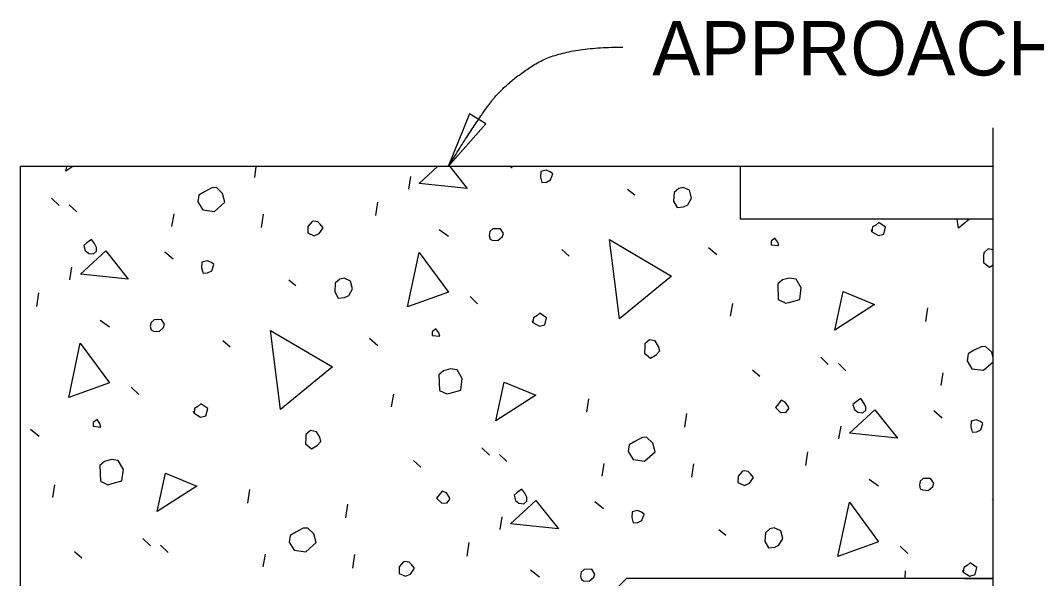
# Model space of a CAD drawing. Extents: x -1660015.2 to -1659984.9, y 2580594.2 to 2580616.7.
# Drawn here: x -1659989.349 to -1659986.525, y 2580613.05 to 2580614.602 of the extents above; entities that cross this region are included whole.
import ezdxf

# ---------------------------------------------------------------- set-up
doc = ezdxf.new("R2010")
doc.units = 0
for name, color, linetype in [('Miscellaneous', 7, 'Continuous'), ('Miscellaneous3', 7, 'Continuous'), ('PlotBorder_dp', 7, 'Continuous'), ('SheetLines_dp', 7, 'Continuous')]:
    doc.layers.add(name, color=color, linetype=linetype)

msp = doc.modelspace()

# ---------------------------------------------------------------- linework, layer by layer
at = {"layer": 'Miscellaneous'}
for p, q in [((-1659988.698, 2580614.1655), (-1659988.6937, 2580614.1954)), ((-1659987.9875, 2580614.1954), (-1659987.9829, 2580614.1915)), ((-1659986.6457, 2580614.1954), (-1659987.3492, 2580614.1954)), ((-1659988.27, 2580614.1327), (-1659988.2639, 2580614.1679)), ((-1659987.6617, 2580614.1326), (-1659987.642, 2580614.1172)), ((-1659989.2622, 2580614.1075), (-1659989.2413, 2580614.0872)), ((-1659989.2134, 2580614.0895), (-1659989.1925, 2580614.0692)), ((-1659988.3615, 2580614.059), (-1659988.3561, 2580614.0967)), ((-1659988.928, 2580614.0288), (-1659988.9219, 2580614.0641)), ((-1659988.6787, 2580614.0257), (-1659988.6733, 2580614.0634)), ((-1659988.1856, 2580614.0207), (-1659988.1598, 2580614.0017)), ((-1659988.948, 2580613.9587), (-1659988.9247, 2580613.9391)), ((-1659987.8444, 2580613.9646), (-1659987.8241, 2580613.9467)), ((-1659987.437, 2580613.9702), (-1659987.4136, 2580613.9506)), ((-1659989.2117, 2580613.8803), (-1659989.2057, 2580613.9156)), ((-1659988.6035, 2580613.8802), (-1659988.5838, 2580613.8648)), ((-1659989.3033, 2580613.8066), (-1659989.2978, 2580613.8443)), ((-1659988.0994, 2580613.8341), (-1659988.0784, 2580613.8139)), ((-1659987.3756, 2580613.7796), (-1659987.3695, 2580613.8149)), ((-1659986.8332, 2580613.7645), (-1659986.8278, 2580613.8022)), ((-1659989.1274, 2580613.7683), (-1659989.1016, 2580613.7494)), ((-1659988.7862, 2580613.7122), (-1659988.7659, 2580613.6944)), ((-1659988.3788, 2580613.7179), (-1659988.3554, 2580613.6982)), ((-1659987.125, 2580613.6656), (-1659987.1041, 2580613.6453)), ((-1659987.0762, 2580613.6476), (-1659987.0553, 2580613.6273)), ((-1659987.3149, 2580613.6302), (-1659987.2946, 2580613.6124)), ((-1659986.7908, 2580613.5869), (-1659986.7847, 2580613.6222)), ((-1659989.0412, 2580613.5818), (-1659989.0202, 2580613.5615)), ((-1659988.3174, 2580613.5273), (-1659988.3113, 2580613.5625)), ((-1659987.775, 2580613.5121), (-1659987.7695, 2580613.5498)), ((-1659987.5026, 2580613.4712), (-1659987.4972, 2580613.5089)), ((-1659986.8108, 2580613.5168), (-1659986.7875, 2580613.4972)), ((-1659989.3206, 2580613.4655), (-1659989.2972, 2580613.4459)), ((-1659987.0745, 2580613.4384), (-1659987.0685, 2580613.4737)), ((-1659988.0668, 2580613.4132), (-1659988.0459, 2580613.393)), ((-1659988.018, 2580613.3952), (-1659987.997, 2580613.375)), ((-1659987.1661, 2580613.3647), (-1659987.1606, 2580613.4024)), ((-1659988.2566, 2580613.3779), (-1659988.2363, 2580613.36)), ((-1659987.7326, 2580613.3346), (-1659987.7265, 2580613.3698)), ((-1659987.4833, 2580613.3315), (-1659987.4779, 2580613.3692)), ((-1659989.2592, 2580613.2749), (-1659989.2531, 2580613.3102)), ((-1659986.9902, 2580613.3264), (-1659986.9644, 2580613.3075)), ((-1659988.7168, 2580613.2598), (-1659988.7113, 2580613.2975)), ((-1659988.4444, 2580613.2189), (-1659988.439, 2580613.2566)), ((-1659987.7526, 2580613.2645), (-1659987.7292, 2580613.2449)), ((-1659986.649, 2580613.2703), (-1659986.6457, 2580613.2674)), ((-1659988.0163, 2580613.1861), (-1659988.0102, 2580613.2213)), ((-1659987.4081, 2580613.186), (-1659987.3884, 2580613.1705)), ((-1659989.0086, 2580613.1609), (-1659988.9876, 2580613.1406)), ((-1659988.9598, 2580613.1429), (-1659988.9388, 2580613.1226)), ((-1659988.1079, 2580613.1124), (-1659988.1024, 2580613.15)), ((-1659986.904, 2580613.1399), (-1659986.883, 2580613.1196)), ((-1659989.1984, 2580613.1255), (-1659989.1781, 2580613.1077)), ((-1659988.6744, 2580613.0822), (-1659988.6683, 2580613.1175)), ((-1659988.4251, 2580613.0791), (-1659988.4196, 2580613.1168)), ((-1659987.932, 2580613.0741), (-1659987.9062, 2580613.0551)), ((-1659986.7243, 2580613.0496), (-1659986.6457, 2580613.0496))]:
    msp.add_line(p, q, dxfattribs=at)
for points in [[(-1659989.2229, 2580614.1827), (-1659989.2202, 2580614.1954)], [(-1659989.2033, 2580614.1954), (-1659989.2229, 2580614.1827)], [(-1659988.2405, 2580614.1483), (-1659988.1899, 2580614.1954)], [(-1659988.1554, 2580614.1954), (-1659988.1075, 2580614.1348), (-1659988.2405, 2580614.1483)], [(-1659987.9036, 2580614.1661), (-1659987.8997, 2580614.1516), (-1659987.887, 2580614.1524), (-1659987.8756, 2580614.1581), (-1659987.8698, 2580614.1752), (-1659987.8766, 2580614.1811), (-1659987.8882, 2580614.1858), (-1659987.9027, 2580614.1819), (-1659987.9036, 2580614.1661)], [(-1659988.8558, 2580614.0973), (-1659988.8421, 2580614.0751), (-1659988.8098, 2580614.0708), (-1659988.7806, 2580614.0968), (-1659988.787, 2580614.1209), (-1659988.8043, 2580614.137), (-1659988.817, 2580614.1362), (-1659988.8374, 2580614.1255), (-1659988.8531, 2580614.1162), (-1659988.8558, 2580614.0973)], [(-1659987.5324, 2580614.1232), (-1659987.5338, 2580614.0996), (-1659987.5238, 2580614.0815), (-1659987.5062, 2580614.0837), (-1659987.4948, 2580614.0893), (-1659987.4842, 2580614.1077), (-1659987.49, 2580614.1294), (-1659987.5078, 2580614.1376), (-1659987.5198, 2580614.1344), (-1659987.5324, 2580614.1232)], [(-1659988.5502, 2580614.0291), (-1659988.5505, 2580614.0109), (-1659988.5328, 2580614.0027), (-1659988.5189, 2580614.009), (-1659988.5077, 2580614.025), (-1659988.5157, 2580614.0357), (-1659988.5225, 2580614.0417), (-1659988.5335, 2580614.0439), (-1659988.5383, 2580614.0426), (-1659988.5502, 2580614.0291)], [(-1659986.7424, 2580614.0243), (-1659986.7456, 2580614.0496)], [(-1659986.7118, 2580614.0496), (-1659986.7424, 2580614.0243)], [(-1659988.0438, 2580613.994), (-1659988.0377, 2580613.9904), (-1659988.0219, 2580613.9895), (-1659988.0094, 2580614.0006), (-1659988.0065, 2580614.0091), (-1659988.0152, 2580614.0223), (-1659988.0358, 2580614.022), (-1659988.0442, 2580614.0146), (-1659988.0464, 2580614.0036), (-1659988.0438, 2580613.994)], [(-1659986.9829, 2580614.0142), (-1659986.9646, 2580614.0036), (-1659986.9501, 2580614.0075), (-1659986.945, 2580614.027), (-1659986.964, 2580614.04), (-1659986.9723, 2580614.0326), (-1659986.9813, 2580614.0276), (-1659986.9829, 2580614.0142), (-1659986.9842, 2580614.0191)], [(-1659989.1688, 2580613.9617), (-1659989.159, 2580613.954), (-1659989.1456, 2580613.9524), (-1659989.1373, 2580613.9598), (-1659989.1374, 2580613.9701), (-1659989.1431, 2580613.9815), (-1659989.1512, 2580613.9923), (-1659989.1643, 2580613.9836), (-1659989.1727, 2580613.9762), (-1659989.1688, 2580613.9617)], [(-1659987.6841, 2580613.772), (-1659987.7121, 2580613.9923), (-1659987.54, 2580613.8909), (-1659987.6841, 2580613.772)], [(-1659987.2631, 2580613.978), (-1659987.2418, 2580613.9759), (-1659987.2444, 2580613.9856), (-1659987.2525, 2580613.9964), (-1659987.2633, 2580613.9883), (-1659987.2631, 2580613.978)], [(-1659989.1823, 2580613.896), (-1659989.1118, 2580613.9614), (-1659989.0492, 2580613.8824), (-1659989.1823, 2580613.896)], [(-1659986.6457, 2580613.9635), (-1659986.6595, 2580613.9663), (-1659986.6721, 2580613.9552), (-1659986.6725, 2580613.9473)], [(-1659988.8454, 2580613.9138), (-1659988.8415, 2580613.8993), (-1659988.8288, 2580613.9001), (-1659988.8174, 2580613.9058), (-1659988.8116, 2580613.9228), (-1659988.8184, 2580613.9288), (-1659988.83, 2580613.9334), (-1659988.8445, 2580613.9296), (-1659988.8454, 2580613.9138)], [(-1659988.2729, 2580613.8058), (-1659988.2409, 2580613.9567), (-1659988.1596, 2580613.8465), (-1659988.2729, 2580613.8058)], [(-1659986.6725, 2580613.9473), (-1659986.6728, 2580613.9291), (-1659986.6562, 2580613.9154), (-1659986.6457, 2580613.9218)], [(-1659988.4742, 2580613.8709), (-1659988.4756, 2580613.8472), (-1659988.4656, 2580613.8292), (-1659988.448, 2580613.8313), (-1659988.4366, 2580613.837), (-1659988.426, 2580613.8553), (-1659988.4318, 2580613.8771), (-1659988.4495, 2580613.8853), (-1659988.4616, 2580613.882), (-1659988.4742, 2580613.8709)], [(-1659987.2443, 2580613.8691), (-1659987.243, 2580613.8255), (-1659987.2222, 2580613.8155), (-1659987.2101, 2580613.8188), (-1659987.1835, 2580613.8259), (-1659987.1792, 2580613.8581), (-1659987.1936, 2580613.8827), (-1659987.2124, 2580613.8854), (-1659987.2318, 2580613.8803), (-1659987.2443, 2580613.8691)], [(-1659987.0857, 2580613.7408), (-1659987.0626, 2580613.8479), (-1659986.9753, 2580613.8118), (-1659987.0857, 2580613.7408)], [(-1659988.9856, 2580613.7416), (-1659988.9795, 2580613.7381), (-1659988.9637, 2580613.7371), (-1659988.9512, 2580613.7483), (-1659988.9483, 2580613.7568), (-1659988.957, 2580613.77), (-1659988.9776, 2580613.7696), (-1659988.986, 2580613.7622), (-1659988.9882, 2580613.7513), (-1659988.9856, 2580613.7416)], [(-1659987.9247, 2580613.7619), (-1659987.9064, 2580613.7513), (-1659987.8919, 2580613.7552), (-1659987.8867, 2580613.7747), (-1659987.9057, 2580613.7877), (-1659987.9141, 2580613.7803), (-1659987.9231, 2580613.7753), (-1659987.9247, 2580613.7619), (-1659987.926, 2580613.7667)], [(-1659988.6259, 2580613.5196), (-1659988.6539, 2580613.7399), (-1659988.4818, 2580613.6385), (-1659988.6259, 2580613.5196)], [(-1659988.2049, 2580613.7256), (-1659988.1836, 2580613.7236), (-1659988.1862, 2580613.7332), (-1659988.1943, 2580613.744), (-1659988.2051, 2580613.7359), (-1659988.2049, 2580613.7256)], [(-1659989.2147, 2580613.5534), (-1659989.1827, 2580613.7043), (-1659989.1014, 2580613.5941), (-1659989.2147, 2580613.5534)], [(-1659987.6143, 2580613.6949), (-1659987.6146, 2580613.6767), (-1659987.598, 2580613.6631), (-1659987.5824, 2580613.6724), (-1659987.5723, 2580613.6829), (-1659987.5755, 2580613.695), (-1659987.5849, 2580613.7106), (-1659987.6013, 2580613.714), (-1659987.6138, 2580613.7028), (-1659987.6143, 2580613.6949)], [(-1659986.6457, 2580613.6635), (-1659986.6498, 2580613.679), (-1659986.6671, 2580613.6951), (-1659986.6798, 2580613.6943), (-1659986.7002, 2580613.6836), (-1659986.7159, 2580613.6743), (-1659986.7186, 2580613.6554)], [(-1659986.7186, 2580613.6554), (-1659986.7049, 2580613.6332), (-1659986.6726, 2580613.6289), (-1659986.6457, 2580613.6528)], [(-1659988.1861, 2580613.6168), (-1659988.1847, 2580613.5732), (-1659988.1639, 2580613.5632), (-1659988.1519, 2580613.5664), (-1659988.1253, 2580613.5736), (-1659988.121, 2580613.6058), (-1659988.1354, 2580613.6304), (-1659988.1542, 2580613.6331), (-1659988.1735, 2580613.6279), (-1659988.1861, 2580613.6168)], [(-1659988.0275, 2580613.4885), (-1659988.0044, 2580613.5956), (-1659987.9171, 2580613.5595), (-1659988.0275, 2580613.4885)], [(-1659988.8665, 2580613.5095), (-1659988.8481, 2580613.4989), (-1659988.8336, 2580613.5028), (-1659988.8285, 2580613.5223), (-1659988.8475, 2580613.5353), (-1659988.8559, 2580613.5279), (-1659988.8649, 2580613.5229), (-1659988.8665, 2580613.5095), (-1659988.8678, 2580613.5144)], [(-1659987.2507, 2580613.5258), (-1659987.2365, 2580613.5115), (-1659987.2213, 2580613.513), (-1659987.2136, 2580613.5228), (-1659987.2149, 2580613.5276), (-1659987.2236, 2580613.5408), (-1659987.2352, 2580613.5455), (-1659987.2429, 2580613.5356), (-1659987.2507, 2580613.5258)], [(-1659987.0316, 2580613.5198), (-1659987.0218, 2580613.5121), (-1659987.0084, 2580613.5105), (-1659987.0001, 2580613.5179), (-1659987.0002, 2580613.5282), (-1659987.0059, 2580613.5396), (-1659987.014, 2580613.5504), (-1659987.0271, 2580613.5417), (-1659987.0355, 2580613.5343), (-1659987.0316, 2580613.5198)], [(-1659987.0451, 2580613.4541), (-1659986.9746, 2580613.5195), (-1659986.912, 2580613.4405), (-1659987.0451, 2580613.4541)], [(-1659989.1467, 2580613.4733), (-1659989.1254, 2580613.4712), (-1659989.128, 2580613.4809), (-1659989.1361, 2580613.4917), (-1659989.1468, 2580613.4836), (-1659989.1467, 2580613.4733)], [(-1659986.7082, 2580613.4719), (-1659986.7043, 2580613.4574), (-1659986.6916, 2580613.4582), (-1659986.6802, 2580613.4638), (-1659986.6744, 2580613.4809), (-1659986.6812, 2580613.4869), (-1659986.6928, 2580613.4915), (-1659986.7073, 2580613.4876), (-1659986.7082, 2580613.4719)], [(-1659988.5561, 2580613.4426), (-1659988.5564, 2580613.4244), (-1659988.5398, 2580613.4107), (-1659988.5242, 2580613.4201), (-1659988.5141, 2580613.4306), (-1659988.5173, 2580613.4426), (-1659988.5266, 2580613.4582), (-1659988.5431, 2580613.4616), (-1659988.5556, 2580613.4505), (-1659988.5561, 2580613.4426)], [(-1659987.6603, 2580613.4031), (-1659987.6466, 2580613.3809), (-1659987.6144, 2580613.3766), (-1659987.5851, 2580613.4025), (-1659987.5916, 2580613.4267), (-1659987.6089, 2580613.4428), (-1659987.6216, 2580613.4419), (-1659987.642, 2580613.4313), (-1659987.6576, 2580613.4219), (-1659987.6603, 2580613.4031)], [(-1659989.1279, 2580613.3644), (-1659989.1265, 2580613.3208), (-1659989.1057, 2580613.3108), (-1659989.0937, 2580613.3141), (-1659989.0671, 2580613.3212), (-1659989.0628, 2580613.3534), (-1659989.0771, 2580613.378), (-1659989.096, 2580613.3808), (-1659989.1153, 2580613.3756), (-1659989.1279, 2580613.3644)], [(-1659988.9692, 2580613.2361), (-1659988.9462, 2580613.3432), (-1659988.8588, 2580613.3071), (-1659988.9692, 2580613.2361)], [(-1659987.3548, 2580613.3348), (-1659987.3551, 2580613.3166), (-1659987.3374, 2580613.3085), (-1659987.3235, 2580613.3148), (-1659987.3123, 2580613.3307), (-1659987.3203, 2580613.3415), (-1659987.3271, 2580613.3474), (-1659987.338, 2580613.3497), (-1659987.3429, 2580613.3484), (-1659987.3548, 2580613.3348)], [(-1659986.8484, 2580613.2997), (-1659986.8423, 2580613.2962), (-1659986.8265, 2580613.2952), (-1659986.814, 2580613.3063), (-1659986.8111, 2580613.3149), (-1659986.8198, 2580613.3281), (-1659986.8404, 2580613.3277), (-1659986.8488, 2580613.3203), (-1659986.851, 2580613.3094), (-1659986.8484, 2580613.2997)], [(-1659988.1924, 2580613.2735), (-1659988.1782, 2580613.2591), (-1659988.1631, 2580613.2606), (-1659988.1554, 2580613.2704), (-1659988.1567, 2580613.2753), (-1659988.1654, 2580613.2885), (-1659988.177, 2580613.2931), (-1659988.1847, 2580613.2833), (-1659988.1924, 2580613.2735)], [(-1659987.9734, 2580613.2674), (-1659987.9636, 2580613.2597), (-1659987.9502, 2580613.2581), (-1659987.9418, 2580613.2655), (-1659987.942, 2580613.2758), (-1659987.9477, 2580613.2873), (-1659987.9557, 2580613.2981), (-1659987.9689, 2580613.2893), (-1659987.9773, 2580613.2819), (-1659987.9734, 2580613.2674)], [(-1659987.9869, 2580613.2017), (-1659987.9164, 2580613.2672), (-1659987.8538, 2580613.1882), (-1659987.9869, 2580613.2017)], [(-1659987.0775, 2580613.1115), (-1659987.0455, 2580613.2624), (-1659986.9642, 2580613.1522), (-1659987.0775, 2580613.1115)], [(-1659987.65, 2580613.2195), (-1659987.6461, 2580613.205), (-1659987.6334, 2580613.2058), (-1659987.622, 2580613.2115), (-1659987.6162, 2580613.2286), (-1659987.6229, 2580613.2345), (-1659987.6345, 2580613.2392), (-1659987.649, 2580613.2353), (-1659987.65, 2580613.2195)], [(-1659988.6021, 2580613.1507), (-1659988.5884, 2580613.1285), (-1659988.5562, 2580613.1242), (-1659988.5269, 2580613.1502), (-1659988.5334, 2580613.1743), (-1659988.5506, 2580613.1904), (-1659988.5634, 2580613.1896), (-1659988.5838, 2580613.1789), (-1659988.5994, 2580613.1696), (-1659988.6021, 2580613.1507)], [(-1659987.2787, 2580613.1766), (-1659987.2802, 2580613.153), (-1659987.2702, 2580613.1349), (-1659987.2526, 2580613.1371), (-1659987.2412, 2580613.1427), (-1659987.2306, 2580613.1611), (-1659987.2364, 2580613.1828), (-1659987.2541, 2580613.191), (-1659987.2662, 2580613.1878), (-1659987.2787, 2580613.1766)], [(-1659988.2966, 2580613.0825), (-1659988.2969, 2580613.0643), (-1659988.2791, 2580613.0561), (-1659988.2653, 2580613.0624), (-1659988.254, 2580613.0784), (-1659988.2621, 2580613.0891), (-1659988.2689, 2580613.0951), (-1659988.2798, 2580613.0973), (-1659988.2847, 2580613.096), (-1659988.2966, 2580613.0825)], [(-1659986.7293, 2580613.0676), (-1659986.7109, 2580613.057), (-1659986.6964, 2580613.0609), (-1659986.6913, 2580613.0804), (-1659986.7103, 2580613.0934), (-1659986.7187, 2580613.086), (-1659986.7277, 2580613.081), (-1659986.7293, 2580613.0676), (-1659986.7306, 2580613.0725)], [(-1659987.7902, 2580613.0474), (-1659987.7841, 2580613.0438), (-1659987.7683, 2580613.0429), (-1659987.7557, 2580613.054), (-1659987.7529, 2580613.0625), (-1659987.7616, 2580613.0757), (-1659987.7822, 2580613.0754), (-1659987.7906, 2580613.068), (-1659987.7928, 2580613.057), (-1659987.7902, 2580613.0474)], [(-1659986.8906, 2580613.0717), (-1659986.8913, 2580613.0496)], [(-1659987.0721, 2580613.0496), (-1659987.0723, 2580613.0505), (-1659987.0746, 2580613.0496)], [(-1659986.9987, 2580613.0496), (-1659986.9989, 2580613.0497), (-1659986.9991, 2580613.0496)]]:
    msp.add_lwpolyline(points, dxfattribs=at)
at = {"layer": 'Miscellaneous3'}
for p, q in [((-1659987.3492, 2580614.1954), (-1659989.3492, 2580614.1954)), ((-1659989.3492, 2580614.1954), (-1659989.3492, 2580612.8204)), ((-1659987.3492, 2580614.1954), (-1659987.3492, 2580614.0496)), ((-1659986.6457, 2580614.0496), (-1659987.3492, 2580614.0496)), ((-1659987.8492, 2580612.8649), (-1659987.6645, 2580613.0496)), ((-1659986.6457, 2580613.0496), (-1659987.6645, 2580613.0496))]:
    msp.add_line(p, q, dxfattribs=at)
at = {"layer": 'SheetLines_dp'}
msp.add_lwpolyline([(-1659988.1604, 2580614.1953), (-1659988.0558, 2580614.3142), (-1659988.1008, 2580614.342)], close=True, dxfattribs=at)
msp.add_lwpolyline([(-1659986.6457, 2580611.2771), (-1659986.6457, 2580611.5436), (-1659986.5682, 2580611.5436), (-1659986.6457, 2580611.5774), (-1659986.7232, 2580611.6111), (-1659986.6457, 2580611.6111), (-1659986.6457, 2580614.3032)], dxfattribs=at)
msp.add_open_spline([(-1659988.1604, 2580614.1953), (-1659988.0783, 2580614.328), (-1659987.9977, 2580614.4309), (-1659987.8425, 2580614.5277), (-1659987.6749, 2580614.5277)], degree=2, dxfattribs=at)

# ---------------------------------------------------------------- texts
at = {"layer": 'PlotBorder_dp'}
msp.add_text('APPROACH SLAB', height=0.1512, dxfattribs=at).set_placement((-1659987.5934, 2580614.4487))

doc.saveas('drawing.dxf')
